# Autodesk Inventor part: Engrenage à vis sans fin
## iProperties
Created: 2011-07
Part Number: Engrenage à vis sans fin
Material: Steel, Mild
Document SubType Name: Modeling
Designer: Laur
Density: 7.86 g/cm^3
CustomPartVersion: 1
Author: Laur
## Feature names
1. Corps de base [Revolution]
2. Dent [Revolution]
3. Motif de la dent [Circular Pattern]
